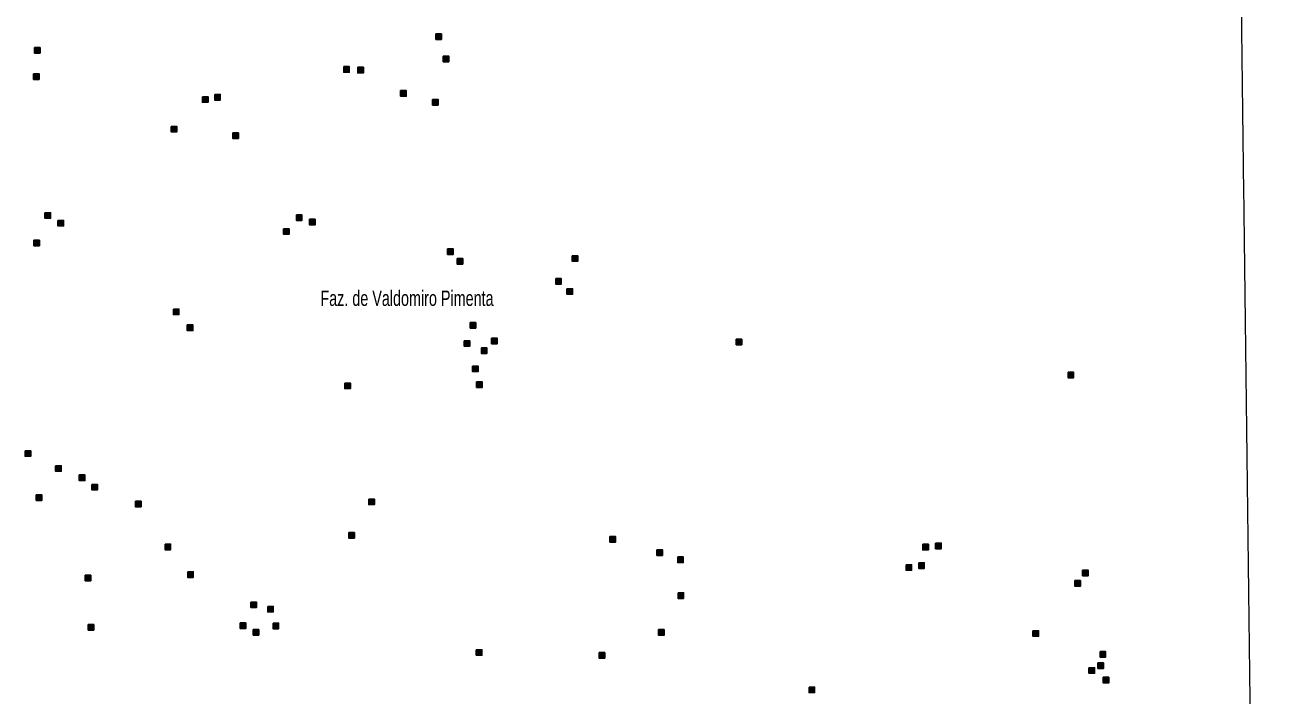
# Model space of a CAD drawing. Extents: x 265.7 to 292.1, y 7676.2 to 7704.2.
# Drawn here: x 285.54 to 292.1, y 7690.19 to 7693.69 of the extents above; entities that cross this region are included whole.
import ezdxf

# ---------------------------------------------------------------- set-up
doc = ezdxf.new("R2010")
doc.units = 0
doc.header["$LTSCALE"] = 0.032
doc.layers.add('2', color=7, linetype='Continuous', lineweight=25)
doc.layers.add('63', color=7, linetype='Continuous', lineweight=13)
doc.layers.add('61', color=7, linetype='Continuous')

msp = doc.modelspace()

# ---------------------------------------------------------------- hatches: boundary and pattern name
at = {"layer": '2'}
for points in [[(287.6843, 7693.645), (287.7133, 7693.645), (287.7133, 7693.616), (287.6843, 7693.616)], [(285.5907, 7693.5739), (285.6197, 7693.5739), (285.6197, 7693.5449), (285.5907, 7693.5449)], [(287.2033, 7693.4739), (287.2323, 7693.4739), (287.2323, 7693.4449), (287.2033, 7693.4449)], [(287.2766, 7693.4706), (287.3056, 7693.4706), (287.3056, 7693.4416), (287.2766, 7693.4416)], [(287.7222, 7693.5288), (287.7512, 7693.5288), (287.7512, 7693.4998), (287.7222, 7693.4998)], [(285.5852, 7693.4367), (285.6142, 7693.4367), (285.6142, 7693.4077), (285.5852, 7693.4077)], [(287.5003, 7693.3487), (287.5293, 7693.3487), (287.5293, 7693.3197), (287.5003, 7693.3197)], [(286.4664, 7693.3173), (286.4954, 7693.3173), (286.4954, 7693.2883), (286.4664, 7693.2883)], [(286.5302, 7693.3287), (286.5592, 7693.3287), (286.5592, 7693.2997), (286.5302, 7693.2997)], [(287.6665, 7693.3027), (287.6955, 7693.3027), (287.6955, 7693.2737), (287.6665, 7693.2737)], [(286.3033, 7693.1623), (286.3323, 7693.1623), (286.3323, 7693.1333), (286.3033, 7693.1333)], [(286.6246, 7693.1285), (286.6536, 7693.1285), (286.6536, 7693.0995), (286.6246, 7693.0995)], [(285.6449, 7692.712), (285.6739, 7692.712), (285.6739, 7692.683), (285.6449, 7692.683)], [(286.9564, 7692.7007), (286.9854, 7692.7007), (286.9854, 7692.6717), (286.9564, 7692.6717)], [(285.7126, 7692.6717), (285.7416, 7692.6717), (285.7416, 7692.6427), (285.7126, 7692.6427)], [(286.8892, 7692.6281), (286.9182, 7692.6281), (286.9182, 7692.5991), (286.8892, 7692.5991)], [(287.0248, 7692.6774), (287.0538, 7692.6774), (287.0538, 7692.6484), (287.0248, 7692.6484)], [(285.5868, 7692.5684), (285.6158, 7692.5684), (285.6158, 7692.5394), (285.5868, 7692.5394)], [(287.7455, 7692.5232), (287.7745, 7692.5232), (287.7745, 7692.4942), (287.7455, 7692.4942)], [(288.3953, 7692.4876), (288.4243, 7692.4876), (288.4243, 7692.4586), (288.3953, 7692.4586)], [(287.7949, 7692.4731), (287.8239, 7692.4731), (287.8239, 7692.4441), (287.7949, 7692.4441)], [(288.3089, 7692.3683), (288.3379, 7692.3683), (288.3379, 7692.3393), (288.3089, 7692.3393)], [(288.3678, 7692.315), (288.3968, 7692.315), (288.3968, 7692.286), (288.3678, 7692.286)], [(286.3147, 7692.2093), (286.3437, 7692.2093), (286.3437, 7692.1803), (286.3147, 7692.1803)], [(286.3874, 7692.1261), (286.4164, 7692.1261), (286.4164, 7692.0971), (286.3874, 7692.0971)], [(287.8634, 7692.1389), (287.8924, 7692.1389), (287.8924, 7692.1099), (287.8634, 7692.1099)], [(287.832, 7692.0438), (287.861, 7692.0438), (287.861, 7692.0148), (287.832, 7692.0148)], [(287.975, 7692.0568), (288.004, 7692.0568), (288.004, 7692.0278), (287.975, 7692.0278)], [(289.2507, 7692.0519), (289.2797, 7692.0519), (289.2797, 7692.0229), (289.2507, 7692.0229)], [(287.9215, 7692.0067), (287.9505, 7692.0067), (287.9505, 7691.9777), (287.9215, 7691.9777)], [(287.8755, 7691.9114), (287.9045, 7691.9114), (287.9045, 7691.8824), (287.8755, 7691.8824)], [(290.9818, 7691.8792), (291.0108, 7691.8792), (291.0108, 7691.8502), (290.9818, 7691.8502)], [(287.2088, 7691.8227), (287.2378, 7691.8227), (287.2378, 7691.7937), (287.2088, 7691.7937)], [(287.8966, 7691.8292), (287.9256, 7691.8292), (287.9256, 7691.8002), (287.8966, 7691.8002)], [(285.5415, 7691.4699), (285.5705, 7691.4699), (285.5705, 7691.4409), (285.5415, 7691.4409)], [(285.7005, 7691.3916), (285.7295, 7691.3916), (285.7295, 7691.3626), (285.7005, 7691.3626)], [(285.8241, 7691.3433), (285.8531, 7691.3433), (285.8531, 7691.3143), (285.8241, 7691.3143)], [(285.8894, 7691.294), (285.9184, 7691.294), (285.9184, 7691.265), (285.8894, 7691.265)], [(285.5997, 7691.2392), (285.6287, 7691.2392), (285.6287, 7691.2102), (285.5997, 7691.2102)], [(286.1169, 7691.2061), (286.1459, 7691.2061), (286.1459, 7691.1771), (286.1169, 7691.1771)], [(287.334, 7691.2174), (287.363, 7691.2174), (287.363, 7691.1884), (287.334, 7691.1884)], [(286.2711, 7690.9824), (286.3001, 7690.9824), (286.3001, 7690.9534), (286.2711, 7690.9534)], [(287.2299, 7691.043), (287.2589, 7691.043), (287.2589, 7691.014), (287.2299, 7691.014)], [(288.5922, 7691.0221), (288.6212, 7691.0221), (288.6212, 7690.9931), (288.5922, 7690.9931)], [(290.2241, 7690.9816), (290.2531, 7690.9816), (290.2531, 7690.9526), (290.2241, 7690.9526)], [(290.291, 7690.9875), (290.32, 7690.9875), (290.32, 7690.9585), (290.291, 7690.9585)], [(288.8367, 7690.9527), (288.8657, 7690.9527), (288.8657, 7690.9237), (288.8367, 7690.9237)], [(288.9457, 7690.9155), (288.9747, 7690.9155), (288.9747, 7690.8865), (288.9457, 7690.8865)], [(290.1368, 7690.8752), (290.1658, 7690.8752), (290.1658, 7690.8462), (290.1368, 7690.8462)], [(290.203, 7690.8849), (290.232, 7690.8849), (290.232, 7690.8559), (290.203, 7690.8559)], [(285.8547, 7690.8203), (285.8837, 7690.8203), (285.8837, 7690.7913), (285.8547, 7690.7913)], [(286.3897, 7690.8381), (286.4187, 7690.8381), (286.4187, 7690.8091), (286.3897, 7690.8091)], [(291.0174, 7690.792), (291.0464, 7690.792), (291.0464, 7690.763), (291.0174, 7690.763)], [(291.0577, 7690.8461), (291.0867, 7690.8461), (291.0867, 7690.8171), (291.0577, 7690.8171)], [(288.9473, 7690.7283), (288.9763, 7690.7283), (288.9763, 7690.6993), (288.9473, 7690.6993)], [(286.719, 7690.6799), (286.748, 7690.6799), (286.748, 7690.6509), (286.719, 7690.6509)], [(286.807, 7690.6573), (286.836, 7690.6573), (286.836, 7690.6283), (286.807, 7690.6283)], [(285.8707, 7690.5628), (285.8997, 7690.5628), (285.8997, 7690.5338), (285.8707, 7690.5338)], [(286.6633, 7690.5709), (286.6923, 7690.5709), (286.6923, 7690.5419), (286.6633, 7690.5419)], [(286.7312, 7690.5365), (286.7602, 7690.5365), (286.7602, 7690.5075), (286.7312, 7690.5075)], [(286.8345, 7690.5702), (286.8635, 7690.5702), (286.8635, 7690.5412), (286.8345, 7690.5412)], [(288.8457, 7690.5362), (288.8747, 7690.5362), (288.8747, 7690.5072), (288.8457, 7690.5072)], [(290.7986, 7690.5306), (290.8276, 7690.5306), (290.8276, 7690.5016), (290.7986, 7690.5016)], [(287.8949, 7690.4314), (287.9239, 7690.4314), (287.9239, 7690.4024), (287.8949, 7690.4024)], [(288.5357, 7690.4168), (288.5647, 7690.4168), (288.5647, 7690.3878), (288.5357, 7690.3878)], [(291.1489, 7690.4217), (291.1779, 7690.4217), (291.1779, 7690.3927), (291.1489, 7690.3927)], [(291.0908, 7690.3376), (291.1198, 7690.3376), (291.1198, 7690.3086), (291.0908, 7690.3086)], [(291.1377, 7690.3627), (291.1667, 7690.3627), (291.1667, 7690.3337), (291.1377, 7690.3337)], [(291.165, 7690.2876), (291.194, 7690.2876), (291.194, 7690.2586), (291.165, 7690.2586)], [(289.6309, 7690.2368), (289.6599, 7690.2368), (289.6599, 7690.2078), (289.6309, 7690.2078)]]:
    msp.add_hatch(color=256, dxfattribs=at).paths.add_polyline_path(points)

# ---------------------------------------------------------------- linework, layer by layer
for points in [[(287.6843, 7693.645), (287.7133, 7693.645), (287.7133, 7693.616), (287.6843, 7693.616)], [(285.5907, 7693.5739), (285.6197, 7693.5739), (285.6197, 7693.5449), (285.5907, 7693.5449)], [(287.2033, 7693.4739), (287.2323, 7693.4739), (287.2323, 7693.4449), (287.2033, 7693.4449)], [(287.2766, 7693.4706), (287.3056, 7693.4706), (287.3056, 7693.4416), (287.2766, 7693.4416)], [(287.7222, 7693.5288), (287.7512, 7693.5288), (287.7512, 7693.4998), (287.7222, 7693.4998)], [(285.5852, 7693.4367), (285.6142, 7693.4367), (285.6142, 7693.4077), (285.5852, 7693.4077)], [(287.5003, 7693.3487), (287.5293, 7693.3487), (287.5293, 7693.3197), (287.5003, 7693.3197)], [(286.4664, 7693.3173), (286.4954, 7693.3173), (286.4954, 7693.2883), (286.4664, 7693.2883)], [(286.5302, 7693.3287), (286.5592, 7693.3287), (286.5592, 7693.2997), (286.5302, 7693.2997)], [(287.6665, 7693.3027), (287.6955, 7693.3027), (287.6955, 7693.2737), (287.6665, 7693.2737)], [(286.3033, 7693.1623), (286.3323, 7693.1623), (286.3323, 7693.1333), (286.3033, 7693.1333)], [(286.6246, 7693.1285), (286.6536, 7693.1285), (286.6536, 7693.0995), (286.6246, 7693.0995)], [(285.6449, 7692.712), (285.6739, 7692.712), (285.6739, 7692.683), (285.6449, 7692.683)], [(286.9564, 7692.7007), (286.9854, 7692.7007), (286.9854, 7692.6717), (286.9564, 7692.6717)], [(285.7126, 7692.6717), (285.7416, 7692.6717), (285.7416, 7692.6427), (285.7126, 7692.6427)], [(286.8892, 7692.6281), (286.9182, 7692.6281), (286.9182, 7692.5991), (286.8892, 7692.5991)], [(287.0248, 7692.6774), (287.0538, 7692.6774), (287.0538, 7692.6484), (287.0248, 7692.6484)], [(285.5868, 7692.5684), (285.6158, 7692.5684), (285.6158, 7692.5394), (285.5868, 7692.5394)], [(287.7455, 7692.5232), (287.7745, 7692.5232), (287.7745, 7692.4942), (287.7455, 7692.4942)], [(288.3953, 7692.4876), (288.4243, 7692.4876), (288.4243, 7692.4586), (288.3953, 7692.4586)], [(287.7949, 7692.4731), (287.8239, 7692.4731), (287.8239, 7692.4441), (287.7949, 7692.4441)], [(288.3089, 7692.3683), (288.3379, 7692.3683), (288.3379, 7692.3393), (288.3089, 7692.3393)], [(288.3678, 7692.315), (288.3968, 7692.315), (288.3968, 7692.286), (288.3678, 7692.286)], [(286.3147, 7692.2093), (286.3437, 7692.2093), (286.3437, 7692.1803), (286.3147, 7692.1803)], [(286.3874, 7692.1261), (286.4164, 7692.1261), (286.4164, 7692.0971), (286.3874, 7692.0971)], [(287.8634, 7692.1389), (287.8924, 7692.1389), (287.8924, 7692.1099), (287.8634, 7692.1099)], [(287.832, 7692.0438), (287.861, 7692.0438), (287.861, 7692.0148), (287.832, 7692.0148)], [(287.975, 7692.0568), (288.004, 7692.0568), (288.004, 7692.0278), (287.975, 7692.0278)], [(289.2507, 7692.0519), (289.2797, 7692.0519), (289.2797, 7692.0229), (289.2507, 7692.0229)], [(287.9215, 7692.0067), (287.9505, 7692.0067), (287.9505, 7691.9777), (287.9215, 7691.9777)], [(287.8755, 7691.9114), (287.9045, 7691.9114), (287.9045, 7691.8824), (287.8755, 7691.8824)], [(290.9818, 7691.8792), (291.0108, 7691.8792), (291.0108, 7691.8502), (290.9818, 7691.8502)], [(287.2088, 7691.8227), (287.2378, 7691.8227), (287.2378, 7691.7937), (287.2088, 7691.7937)], [(287.8966, 7691.8292), (287.9256, 7691.8292), (287.9256, 7691.8002), (287.8966, 7691.8002)], [(285.5415, 7691.4699), (285.5705, 7691.4699), (285.5705, 7691.4409), (285.5415, 7691.4409)], [(285.7005, 7691.3916), (285.7295, 7691.3916), (285.7295, 7691.3626), (285.7005, 7691.3626)], [(285.8241, 7691.3433), (285.8531, 7691.3433), (285.8531, 7691.3143), (285.8241, 7691.3143)], [(285.8894, 7691.294), (285.9184, 7691.294), (285.9184, 7691.265), (285.8894, 7691.265)], [(285.5997, 7691.2392), (285.6287, 7691.2392), (285.6287, 7691.2102), (285.5997, 7691.2102)], [(286.1169, 7691.2061), (286.1459, 7691.2061), (286.1459, 7691.1771), (286.1169, 7691.1771)], [(287.334, 7691.2174), (287.363, 7691.2174), (287.363, 7691.1884), (287.334, 7691.1884)], [(286.2711, 7690.9824), (286.3001, 7690.9824), (286.3001, 7690.9534), (286.2711, 7690.9534)], [(287.2299, 7691.043), (287.2589, 7691.043), (287.2589, 7691.014), (287.2299, 7691.014)], [(288.5922, 7691.0221), (288.6212, 7691.0221), (288.6212, 7690.9931), (288.5922, 7690.9931)], [(290.2241, 7690.9816), (290.2531, 7690.9816), (290.2531, 7690.9526), (290.2241, 7690.9526)], [(290.291, 7690.9875), (290.32, 7690.9875), (290.32, 7690.9585), (290.291, 7690.9585)], [(288.8367, 7690.9527), (288.8657, 7690.9527), (288.8657, 7690.9237), (288.8367, 7690.9237)], [(288.9457, 7690.9155), (288.9747, 7690.9155), (288.9747, 7690.8865), (288.9457, 7690.8865)], [(290.1368, 7690.8752), (290.1658, 7690.8752), (290.1658, 7690.8462), (290.1368, 7690.8462)], [(290.203, 7690.8849), (290.232, 7690.8849), (290.232, 7690.8559), (290.203, 7690.8559)], [(285.8547, 7690.8203), (285.8837, 7690.8203), (285.8837, 7690.7913), (285.8547, 7690.7913)], [(286.3897, 7690.8381), (286.4187, 7690.8381), (286.4187, 7690.8091), (286.3897, 7690.8091)], [(291.0174, 7690.792), (291.0464, 7690.792), (291.0464, 7690.763), (291.0174, 7690.763)], [(291.0577, 7690.8461), (291.0867, 7690.8461), (291.0867, 7690.8171), (291.0577, 7690.8171)], [(288.9473, 7690.7283), (288.9763, 7690.7283), (288.9763, 7690.6993), (288.9473, 7690.6993)], [(286.719, 7690.6799), (286.748, 7690.6799), (286.748, 7690.6509), (286.719, 7690.6509)], [(286.807, 7690.6573), (286.836, 7690.6573), (286.836, 7690.6283), (286.807, 7690.6283)], [(285.8707, 7690.5628), (285.8997, 7690.5628), (285.8997, 7690.5338), (285.8707, 7690.5338)], [(286.6633, 7690.5709), (286.6923, 7690.5709), (286.6923, 7690.5419), (286.6633, 7690.5419)], [(286.7312, 7690.5365), (286.7602, 7690.5365), (286.7602, 7690.5075), (286.7312, 7690.5075)], [(286.8345, 7690.5702), (286.8635, 7690.5702), (286.8635, 7690.5412), (286.8345, 7690.5412)], [(288.8457, 7690.5362), (288.8747, 7690.5362), (288.8747, 7690.5072), (288.8457, 7690.5072)], [(290.7986, 7690.5306), (290.8276, 7690.5306), (290.8276, 7690.5016), (290.7986, 7690.5016)], [(287.8949, 7690.4314), (287.9239, 7690.4314), (287.9239, 7690.4024), (287.8949, 7690.4024)], [(288.5357, 7690.4168), (288.5647, 7690.4168), (288.5647, 7690.3878), (288.5357, 7690.3878)], [(291.1489, 7690.4217), (291.1779, 7690.4217), (291.1779, 7690.3927), (291.1489, 7690.3927)], [(291.0908, 7690.3376), (291.1198, 7690.3376), (291.1198, 7690.3086), (291.0908, 7690.3086)], [(291.1377, 7690.3627), (291.1667, 7690.3627), (291.1667, 7690.3337), (291.1377, 7690.3337)], [(291.165, 7690.2876), (291.194, 7690.2876), (291.194, 7690.2586), (291.165, 7690.2586)], [(289.6309, 7690.2368), (289.6599, 7690.2368), (289.6599, 7690.2078), (289.6309, 7690.2078)]]:
    msp.add_lwpolyline(points, close=True, dxfattribs=at)
at = {"layer": '63'}
msp.add_spline([(292.1022, 7676.5221), (292.0951, 7677.087), (292.088, 7677.6519), (292.081, 7678.2168), (292.0739, 7678.7818), (292.0668, 7679.3467), (292.0598, 7679.9116), (292.0527, 7680.4765), (292.0457, 7681.0414), (292.0386, 7681.6064), (292.0316, 7682.1713), (292.0245, 7682.7362), (292.0175, 7683.3011), (292.0104, 7683.866), (292.0034, 7684.431), (291.9963, 7684.9959), (291.9893, 7685.5608), (291.9822, 7686.1257), (291.9752, 7686.6906), (291.9681, 7687.2556), (291.9611, 7687.8205), (291.9541, 7688.3854), (291.947, 7688.9503), (291.94, 7689.5152), (291.933, 7690.0801), (291.9259, 7690.6451), (291.9189, 7691.21), (291.9119, 7691.7749), (291.9049, 7692.3398), (291.8978, 7692.9047), (291.8908, 7693.4696), (291.8838, 7694.0345), (291.8768, 7694.5995), (291.8698, 7695.1644), (291.8628, 7695.7293), (291.8557, 7696.2942), (291.8487, 7696.8591), (291.8417, 7697.424), (291.8347, 7697.9889), (291.8277, 7698.5539), (291.8207, 7699.1188), (291.8137, 7699.6837), (291.8067, 7700.2486), (291.7997, 7700.8135), (291.7927, 7701.3784), (291.7857, 7701.9433), (291.7787, 7702.5082), (291.7717, 7703.0731), (291.7647, 7703.638), (291.7577, 7704.203)], degree=3, dxfattribs=at)

# ---------------------------------------------------------------- texts
at = {"layer": '61', "width": 0.7}
msp.add_text('Faz. de Valdomiro Pimenta', height=0.08, dxfattribs=at).set_placement((287.0818, 7692.2255))

doc.saveas('drawing.dxf')
